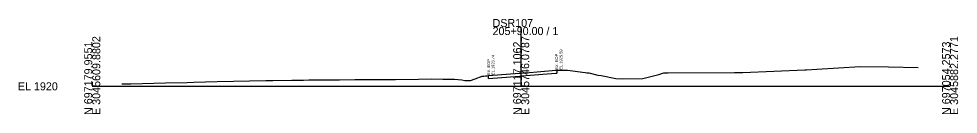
# Model space of a CAD drawing. Extents: x -26 to 19003, y -31 to 24541.
# Drawn here: x 1974.3 to 2302.8, y 6490.3 to 6523.5 of the extents above; entities that cross this region are included whole.
import ezdxf

# ---------------------------------------------------------------- set-up
doc = ezdxf.new("R2010")
doc.units = 0
for name, color, linetype in [('DESIGN - SHEET - Light Grid', 7, 'Continuous'), ('SURVEY - GROUND - Existing Pavement Layer', 7, 'Continuous'), ('SURVEY - GROUND - Existing Pavement Text', 7, 'Continuous'), ('SURVEY - GROUND - Top of Ground', 7, 'Continuous')]:
    doc.layers.add(name, color=color, linetype=linetype)

msp = doc.modelspace()

# ---------------------------------------------------------------- linework, layer by layer
at = {"layer": 'DESIGN - SHEET - Light Grid'}
for p, q in [((2150, 6500), (2150, 6520.66)), ((2000, 6500), (2150, 6500)), ((2150, 6500), (2300, 6500))]:
    msp.add_line(p, q, dxfattribs=at)
at = {"layer": 'SURVEY - GROUND - Existing Pavement Layer'}
for p, q in [((2162.42, 6505.59), (2162.42, 6504.59)), ((2138.63, 6502.74), (2138.63, 6503.74)), ((2138.63, 6502.74), (2149.47, 6503.57)), ((2149.47, 6503.57), (2150, 6503.61)), ((2150, 6503.61), (2150.71, 6503.67)), ((2150.71, 6503.67), (2151.68, 6503.75)), ((2151.68, 6503.75), (2162.09, 6504.58)), ((2162.09, 6504.58), (2162.42, 6504.59))]:
    msp.add_line(p, q, dxfattribs=at)
at = {"layer": 'SURVEY - GROUND - Top of Ground'}
msp.add_lwpolyline([(2010.29, 6500.82), (2013.47, 6500.88), (2025.56, 6501.17), (2033.23, 6501.37), (2035.5, 6501.48), (2043.74, 6501.63), (2060.69, 6502.07), (2063.14, 6502.05), (2069.76, 6502.09), (2072.45, 6502.11), (2073.84, 6502.18), (2075.74, 6502.23), (2083.75, 6502.24), (2086.41, 6502.22), (2091.78, 6502.33), (2097.21, 6502.41), (2106.06, 6502.41), (2114.06, 6502.48), (2118.51, 6502.59), (2122.61, 6502.51), (2126.67, 6502.51), (2129.24, 6502.21), (2130.27, 6502.05), (2130.96, 6502.06), (2132.24, 6502.07), (2133.92, 6502.63), (2136.36, 6503.5), (2136.97, 6503.57), (2137.58, 6503.62), (2138.13, 6503.68), (2138.63, 6503.74), (2149.47, 6504.57), (2150, 6504.61), (2150.71, 6504.67), (2151.68, 6504.75), (2162.09, 6505.58), (2162.42, 6505.59), (2163.64, 6505.67), (2166.22, 6505.63), (2172.38, 6504.86), (2172.99, 6504.73), (2173.61, 6504.67), (2176.77, 6503.89), (2178, 6503.77), (2183.14, 6502.68), (2185.57, 6502.65), (2192.53, 6502.72), (2198.14, 6504.17), (2199.92, 6504.74), (2201.44, 6504.74), (2224.62, 6504.81), (2227.53, 6504.87), (2249.15, 6505.72), (2249.79, 6505.8), (2253.45, 6505.99), (2268.59, 6506.89), (2278.5, 6506.83), (2288.89, 6506.51)], dxfattribs=at)

# ---------------------------------------------------------------- texts
at = {"layer": 'DESIGN - SHEET - Light Grid'}
for s, p in [('DSR107', (2140, 6520.66)), ('205+90.00 / 1', (2140, 6517.86)), ('EL 1920', (1974, 6498.6))]:
    msp.add_text(s, height=2.8, dxfattribs=at).set_placement(p)
for s, p in [('N 697179.9551', (2000, 6490)), ('E 3045609.8802', (2002.8, 6490)), ('N 697117.1062', (2150, 6490)), ('E 3045746.0787', (2152.8, 6490)), ('N 697054.2573', (2300, 6490)), ('E 3045882.2771', (2302.8, 6490))]:
    msp.add_text(s, height=2.8, rotation=90, dxfattribs=at).set_placement(p)
at = {"layer": 'SURVEY - GROUND - Existing Pavement Text'}
for s, p in [('EL.1925.59', (2164.42, 6505.79)), ('EX. EOP', (2139.13, 6503.94)), ('EL.1923.74', (2140.63, 6503.94)), ('EX. EOP', (2162.92, 6505.79))]:
    msp.add_text(s, height=1, rotation=90, dxfattribs=at).set_placement(p)

doc.saveas('drawing.dxf')
